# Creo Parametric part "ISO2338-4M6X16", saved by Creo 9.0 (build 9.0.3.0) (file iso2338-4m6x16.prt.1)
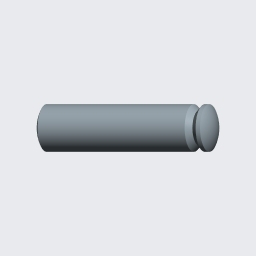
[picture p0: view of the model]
Units: millimeter Kilogram Sec (mmKs); MM, KILOGRAM, SECS
Materials in the file: STAHL

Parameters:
  WERKSTOFF = "Stahl"
  ERSTELLER = "ARINDA"
  BENENNUNG = "XXX"
  TEILETYP = "K"
  PTC_MASTER_MATERIAL = "STAHL"

Other parameters: MASSE

Created from: ARINDA_STARTTEIL.PRT

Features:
  1. coordinate system
  2. datum plane "RECHTS_Y-Z"
  3. datum plane "OBEN_X-Z"
  4. datum plane "VORNE_X-Y"
  5. datum axis
  6. datum axis
  7. datum axis
  8. datum point "PNT0"
  9. revolve "Drehen 1"
  10. revolved cut "Drehen 2"

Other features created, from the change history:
  coordinate system "CS1"

Other named items: A_X, A_Y, A_Z, CS0

Layers: 01_ACHSEN_STD, 01_EBENEN_STD, 01_KOORDSYS_STD, 01_PUNKTE_STD, VOLUMENGEOMETRIE

Surfaces: 4 torus, 4 cone, 2 cylinder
